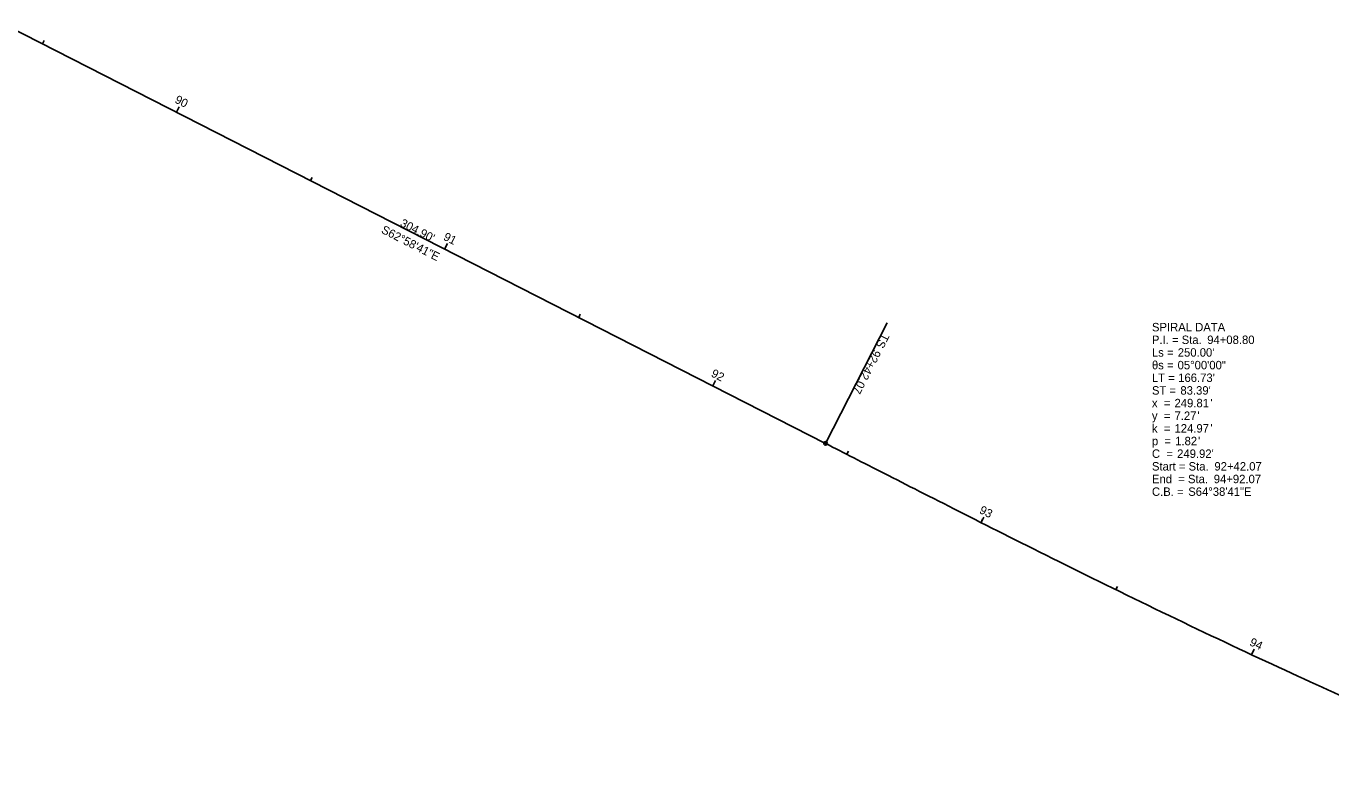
# Model space of a CAD drawing. Extents: x 1999336 to 2003366, y 252766 to 253936.
# Drawn here: x 2001610.2 to 2002043.7, y 252870.6 to 253116.2 of the extents above; entities that cross this region are included whole.
import ezdxf

# ---------------------------------------------------------------- set-up
doc = ezdxf.new("R2010")
doc.units = 0
for name, color, linetype in [('GE_X_CL_20', 7, 'Continuous'), ('GK_Visualization', 7, 'Continuous'), ('RW_X_Esmt_SH', 7, 'Continuous'), ('SC_Scratch3', 7, 'Continuous'), ('SV_X_Control_Cells_Found', 7, 'Continuous'), ('SV_X_Text_Elevation', 7, 'Continuous'), ('SV_X_Text_Name', 7, 'Continuous')]:
    doc.layers.add(name, color=color, linetype=linetype)

msp = doc.modelspace()

# ---------------------------------------------------------------- linework, layer by layer
at = {"layer": 'GE_X_CL_20'}
for p, q in [((2001660.21, 253087.61), (2001661.12, 253089.39)), ((2001749.29, 253042.17), (2001749.84, 253043.24)), ((2001875.85, 252977.63), (2001896.29, 253017.72)), ((2001838.37, 252996.74), (2001838.92, 252997.81)), ((2001927.5, 252951.39), (2001928.04, 252952.46)), ((2002017.36, 252907.52), (2002017.86, 252908.6))]:
    msp.add_line(p, q, dxfattribs=at)
msp.add_circle((2001875.85, 252977.63), 0.6, dxfattribs=at)
at = {"layer": 'GK_Visualization'}
msp.add_line((2001604.23, 253116.16), (2001875.85, 252977.63), dxfattribs=at)
msp.add_open_spline([(2001875.85, 252977.63), (2001882.03, 252974.47), (2001894.41, 252968.16), (2001919.17, 252955.57), (2001950.18, 252939.95), (2001987.57, 252921.56), (2002025.22, 252903.72), (2002056.88, 252889.46), (2002082.41, 252878.51), (2002095.25, 252873.21), (2002101.69, 252870.61)], degree=3, dxfattribs=at)
msp.add_open_spline([(2001875.85, 252977.63), (2001882.03, 252974.47), (2001894.41, 252968.16), (2001919.17, 252955.57), (2001950.18, 252939.95), (2001987.57, 252921.56), (2002025.22, 252903.72), (2002056.88, 252889.46), (2002082.41, 252878.51), (2002095.25, 252873.21), (2002101.69, 252870.61)], degree=3, dxfattribs=at)
at = {"layer": 'SC_Scratch3'}
for p, q in [((2001615.67, 253110.32), (2001616.21, 253111.39)), ((2001660.21, 253087.61), (2001661.12, 253089.39)), ((2001704.75, 253064.89), (2001705.29, 253065.96)), ((2001749.29, 253042.17), (2001750.2, 253043.96)), ((2001793.83, 253019.46), (2001794.38, 253020.53)), ((2001875.85, 252977.63), (2001896.29, 253017.72)), ((2001838.37, 252996.74), (2001839.28, 252998.52)), ((2001882.92, 252974.03), (2001883.46, 252975.09)), ((2001927.5, 252951.39), (2001928.4, 252953.18)), ((2001972.26, 252929.11), (2001972.79, 252930.19)), ((2002017.36, 252907.52), (2002018.2, 252909.33))]:
    msp.add_line(p, q, dxfattribs=at)
msp.add_circle((2001875.85, 252977.63), 0.6, dxfattribs=at)
at = {"layer": 'SV_X_Text_Name'}
for p, q in [((2001660.21, 253087.61), (2001661.12, 253089.39)), ((2001875.85, 252977.63), (2001896.29, 253017.72))]:
    msp.add_line(p, q, dxfattribs=at)
msp.add_circle((2001875.85, 252977.63), 0.6, dxfattribs=at)

# ---------------------------------------------------------------- texts
at = {"layer": 'GE_X_CL_20'}
for s, rotation, p in [('90', 332.9781, (2001659.41, 253090.87)), ("304.90'", 332.9781, (2001734.28, 253049.88)), ('S62°58\'41"E', 332.9781, (2001727.99, 253047.65)), ('TS', 242.9781, (2001894.67, 253014.43)), ('92+42.07', 242.9781, (2001891.9, 253009))]:
    msp.add_text(s, height=2.8, rotation=rotation, dxfattribs=at).set_placement(p)
at = {"layer": 'RW_X_Esmt_SH'}
for s, p in [('SPIRAL DATA', (2001984.28, 253014.84)), ('P.I. = Sta. ', (2001984.28, 253010.64)), ('94+08.80', (2002002.65, 253010.64)), ('Ls = ', (2001984.28, 253006.44)), ("250.00'", (2001992.87, 253006.44)), ('θs = ', (2001984.28, 253002.24)), ('05°00\'00"', (2001992.81, 253002.24)), ('LT = ', (2001984.28, 252998.04)), ("166.73'", (2001993.01, 252998.04)), ('ST = ', (2001984.28, 252993.84)), ("83.39'", (2001993.74, 252993.84)), ('x  = ', (2001984.28, 252989.64)), ('249.81', (2001991.78, 252989.64)), ("'", (2002003.74, 252989.64)), ('y  = ', (2001984.28, 252985.44)), ('7.27', (2001991.78, 252985.44)), ("'", (2001999.39, 252985.44)), ('k  = ', (2001984.28, 252981.24)), ('124.97', (2001991.78, 252981.24)), ("'", (2002003.74, 252981.24)), ('p  = ', (2001984.28, 252977.04)), ('1.82', (2001992, 252977.04)), ("'", (2001999.61, 252977.04)), ('C  = ', (2001984.28, 252972.84)), ("249.92'", (2001992.65, 252972.84)), ('Start = Sta. ', (2001984.28, 252968.64)), ('92+42.07', (2002005.04, 252968.64)), ('End  = Sta. ', (2001984.28, 252964.44)), ('94+92.07', (2002004.82, 252964.44)), ('C.B. = ', (2001984.28, 252960.24)), ('S64°38\'41"E', (2001996.34, 252960.24))]:
    msp.add_text(s, height=2.8, dxfattribs=at).set_placement(p)
at = {"layer": 'SC_Scratch3'}
for s, rotation, p in [('90', 332.9781, (2001659.41, 253090.87)), ("304.90'", 332.9781, (2001734.28, 253049.88)), ('S62°58\'41"E', 332.9781, (2001727.99, 253047.65)), ('91', 332.9781, (2001748.64, 253045.36)), ('TS', 242.9781, (2001894.67, 253014.43)), ('92+42.07', 242.9781, (2001891.9, 253009)), ('92', 332.9781, (2001837.58, 253000)), ('93', 333.2466, (2001926.7, 252954.64)), ('94', 334.9735, (2002016.48, 252910.74))]:
    msp.add_text(s, height=2.8, rotation=rotation, dxfattribs=at).set_placement(p)
at = {"layer": 'SV_X_Control_Cells_Found'}
for s, p in [('SPIRAL DATA', (2001984.28, 253014.84)), ('P.I. = Sta. ', (2001984.28, 253010.64)), ('94+08.80', (2002002.65, 253010.64)), ('Ls = ', (2001984.28, 253006.44)), ("250.00'", (2001992.87, 253006.44)), ('θs = ', (2001984.28, 253002.24)), ('05°00\'00"', (2001992.81, 253002.24)), ('LT = ', (2001984.28, 252998.04)), ("166.73'", (2001993.01, 252998.04)), ('ST = ', (2001984.28, 252993.84)), ("83.39'", (2001993.74, 252993.84)), ('x  = ', (2001984.28, 252989.64)), ('249.81', (2001991.78, 252989.64)), ("'", (2002003.74, 252989.64)), ('y  = ', (2001984.28, 252985.44)), ('7.27', (2001991.78, 252985.44)), ("'", (2001999.39, 252985.44)), ('k  = ', (2001984.28, 252981.24)), ('124.97', (2001991.78, 252981.24)), ("'", (2002003.74, 252981.24)), ('p  = ', (2001984.28, 252977.04)), ('1.82', (2001992, 252977.04)), ("'", (2001999.61, 252977.04)), ('C  = ', (2001984.28, 252972.84)), ("249.92'", (2001992.65, 252972.84)), ('Start = Sta. ', (2001984.28, 252968.64)), ('92+42.07', (2002005.04, 252968.64)), ('End  = Sta. ', (2001984.28, 252964.44)), ('94+92.07', (2002004.82, 252964.44)), ('C.B. = ', (2001984.28, 252960.24)), ('S64°38\'41"E', (2001996.34, 252960.24))]:
    msp.add_text(s, height=2.8, dxfattribs=at).set_placement(p)
at = {"layer": 'SV_X_Text_Elevation'}
for s, p in [('SPIRAL DATA', (2001984.28, 253014.84)), ('P.I. = Sta. ', (2001984.28, 253010.64)), ('94+08.80', (2002002.65, 253010.64)), ('Ls = ', (2001984.28, 253006.44)), ("250.00'", (2001992.87, 253006.44)), ('θs = ', (2001984.28, 253002.24)), ('05°00\'00"', (2001992.81, 253002.24)), ('LT = ', (2001984.28, 252998.04)), ("166.73'", (2001993.01, 252998.04)), ('ST = ', (2001984.28, 252993.84)), ("83.39'", (2001993.74, 252993.84)), ('x  = ', (2001984.28, 252989.64)), ('249.81', (2001991.78, 252989.64)), ("'", (2002003.74, 252989.64)), ('y  = ', (2001984.28, 252985.44)), ('7.27', (2001991.78, 252985.44)), ("'", (2001999.39, 252985.44)), ('k  = ', (2001984.28, 252981.24)), ('124.97', (2001991.78, 252981.24)), ("'", (2002003.74, 252981.24)), ('p  = ', (2001984.28, 252977.04)), ('1.82', (2001992, 252977.04)), ("'", (2001999.61, 252977.04)), ('C  = ', (2001984.28, 252972.84)), ("249.92'", (2001992.65, 252972.84)), ('Start = Sta. ', (2001984.28, 252968.64)), ('92+42.07', (2002005.04, 252968.64)), ('End  = Sta. ', (2001984.28, 252964.44)), ('94+92.07', (2002004.82, 252964.44)), ('C.B. = ', (2001984.28, 252960.24)), ('S64°38\'41"E', (2001996.34, 252960.24))]:
    msp.add_text(s, height=2.8, dxfattribs=at).set_placement(p)
at = {"layer": 'SV_X_Text_Name'}
for s, rotation, p in [('90', 332.9781, (2001659.41, 253090.87)), ("304.90'", 332.9781, (2001734.28, 253049.88)), ('S62°58\'41"E', 332.9781, (2001727.99, 253047.65)), ('TS', 242.9781, (2001894.67, 253014.43)), ('92+42.07', 242.9781, (2001891.9, 253009))]:
    msp.add_text(s, height=2.8, rotation=rotation, dxfattribs=at).set_placement(p)

doc.saveas('drawing.dxf')
